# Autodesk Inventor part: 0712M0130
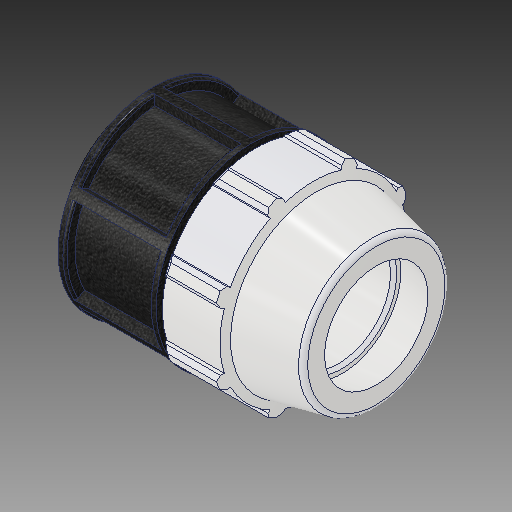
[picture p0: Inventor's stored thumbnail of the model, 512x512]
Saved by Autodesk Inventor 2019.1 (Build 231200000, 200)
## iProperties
Created: 2017-02
Part Number: 0712M0130
Material: PVC-Piping
Description: PLASSON END PLUG 1 1/4''
Document SubType Name: Modeling
Designer: KIM
Mass: 92.6774 g
Surface Area: 199.44 cm^2
Volume: 66.1981 cm^3
Density: 1.4 g/cm^3
Appearance: PTFE
Author: Кирилл
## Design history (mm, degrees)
derived "0712M0.ipt"
feature "Solid1::0712M0.ipt"
tag "TaggingFeature1"
body "Solid1"
other parameters: "d2" = 42.1, "d4" = 14.00629, "d5" = 24.511, "d7" = 82.042, "d8" = 69.7357, "d9" = 14.00629, "d11" = 2.80126, "d12" = 69.7357, "d13" = 120 deg, "d15" = 12 deg, "d16" = 77.9399, "d18" = 2.105, "d19" = 35 deg, "d20" = 17.5 deg, "d21" = 76.29906, "d23" = 0, "d25" = 360 deg, "d27" = 1.64084, "d34" = 4.1021, "d36" = 0, "d42" = 24.511, "d43" = 2.46126, "d46" = 1.263, "d53" = 0.842, "d55" = 360 deg, "d59" = 34.3154, "d64" = 98.044, "d66" = 8.2042, "d67" = 4.1021, "d68" = 87.884, "d70" = 69.7357, "d_" = 42.1, "E_" = 82.042, "H_" = 98.044, "l_" = 87.884
